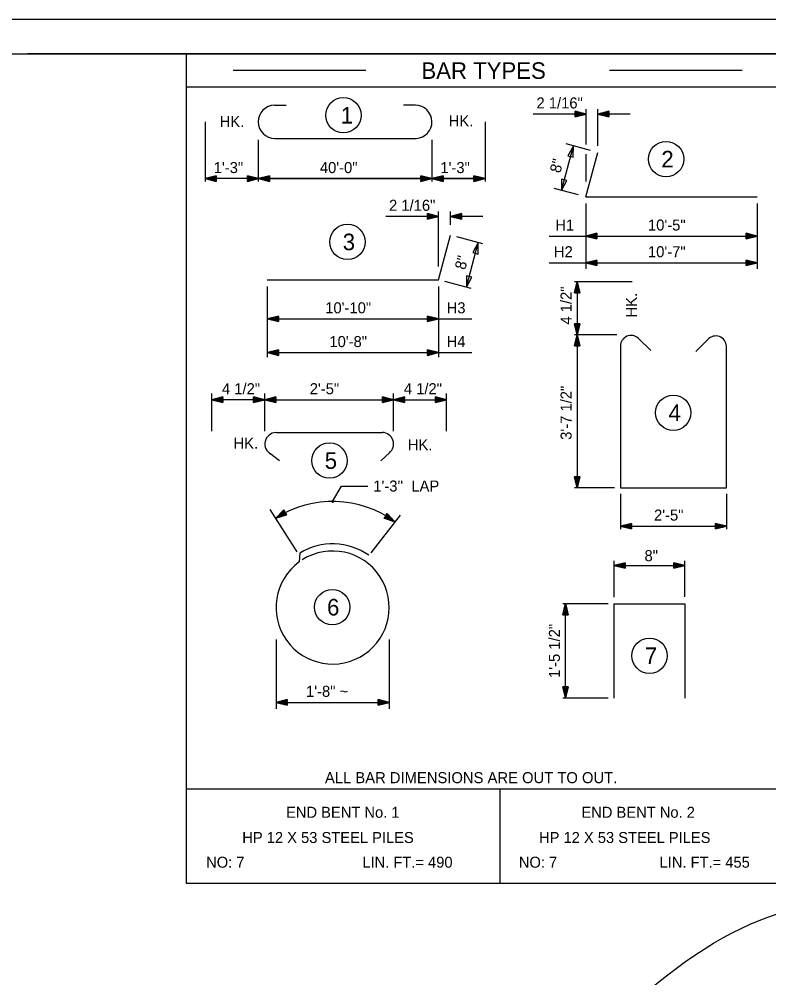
# Model space of a CAD drawing. Extents: x -41 to 191, y -168 to 6.
# Drawn here: x 45.29 to 64.69, y -142.92 to -118.09 of the extents above; entities that cross this region are included whole.
import ezdxf

# ---------------------------------------------------------------- set-up
doc = ezdxf.new("R2010")
doc.units = 0
for name, color, linetype in [('Arrowhead Terminators CELL', 7, 'Continuous'), ('Dimension Lines', 7, 'Continuous'), ('Dimension Lines CELL', 7, 'Continuous'), ('Plan Sheet CELL', 7, 'Continuous'), ('Plot Shape CELL', 7, 'Continuous'), ('Rebar Lines', 7, 'Continuous'), ('Rebar Lines CELL', 7, 'Continuous'), ('Subtitle Text', 7, 'Continuous'), ('Text', 7, 'Continuous'), ('Text CELL', 7, 'Continuous'), ('User Information Notes', 7, 'Continuous')]:
    doc.layers.add(name, color=color, linetype=linetype)

msp = doc.modelspace()

# ---------------------------------------------------------------- linework, layer by layer
at = {"layer": 'Arrowhead Terminators CELL'}
for points in [[(59.631, -121.373), (59.488, -121.631), (59.627, -121.668)], [(59.322, -122.528), (59.465, -122.27), (59.327, -122.233)], [(57.17, -123.88), (57.027, -124.138), (57.165, -124.175)], [(56.861, -125.035), (57.004, -124.777), (56.866, -124.74)]]:
    msp.add_lwpolyline(points, close=True, dxfattribs=at)
at = {"layer": 'Dimension Lines'}
for p, q in [((59.96, -120.549), (58.588, -120.549)), ((59.96, -121.342), (59.96, -120.422)), ((60.263, -121.376), (60.263, -120.422)), ((61.103, -120.549), (60.263, -120.549)), ((59.322, -122.528), (59.631, -121.373)), ((60.071, -121.491), (59.44, -121.322)), ((59.96, -122.3), (59.96, -121.589)), ((59.762, -122.645), (59.13, -122.476)), ((56.143, -124.497), (56.143, -123.071)), ((56.446, -123.423), (56.446, -123.071)), ((56.143, -123.199), (54.772, -123.199)), ((57.287, -123.199), (56.446, -123.199)), ((57.29, -123.912), (56.613, -123.731)), ((56.861, -125.035), (57.17, -123.88)), ((56.981, -125.067), (56.304, -124.886))]:
    msp.add_line(p, q, dxfattribs=at)
at = {"layer": 'Dimension Lines CELL'}
for p, q in [((50.101, -120.751), (50.101, -122.294)), ((57.343, -120.751), (57.343, -122.294)), ((51.474, -121.219), (51.474, -122.294)), ((55.97, -121.219), (55.97, -122.294)), ((51.479, -122.222), (50.101, -122.222)), ((51.479, -122.222), (55.97, -122.222)), ((57.114, -122.222), (51.479, -122.222)), ((55.97, -122.222), (57.343, -122.222)), ((59.955, -122.869), (59.955, -124.556)), ((64.385, -122.869), (64.385, -124.556)), ((59.005, -123.71), (64.385, -123.71)), ((59.005, -124.401), (64.385, -124.401)), ((51.709, -125.014), (51.709, -126.846)), ((56.139, -125.014), (56.139, -126.846)), ((61.15, -124.893), (59.656, -124.893)), ((59.727, -124.893), (59.727, -126.266)), ((51.71, -125.854), (57.002, -125.854)), ((60.751, -126.266), (59.656, -126.266)), ((59.727, -126.266), (59.727, -130.23)), ((51.71, -126.728), (57.002, -126.728)), ((50.274, -128.762), (50.274, -127.783)), ((51.646, -128.762), (51.646, -127.783)), ((54.977, -128.762), (54.977, -127.783)), ((56.35, -128.762), (56.35, -127.783)), ((51.641, -127.949), (50.274, -127.949)), ((51.641, -127.949), (54.977, -127.949)), ((54.977, -127.949), (56.35, -127.949)), ((53.399, -130.585), (53.628, -130.188)), ((53.628, -130.188), (54.314, -130.188)), ((60.693, -130.23), (59.656, -130.23)), ((60.846, -130.383), (60.846, -131.298)), ((63.592, -130.383), (63.592, -131.298)), ((52.483, -131.888), (51.786, -130.79)), ((55.151, -130.94), (54.392, -131.91)), ((60.846, -131.222), (63.592, -131.222)), ((60.686, -133.063), (60.686, -132.12)), ((60.686, -132.241), (62.516, -132.241)), ((62.516, -133.055), (62.516, -132.12)), ((60.533, -133.238), (59.354, -133.238)), ((59.425, -135.67), (59.425, -133.238)), ((51.934, -134.161), (51.934, -135.955)), ((54.863, -134.161), (54.863, -135.955)), ((51.939, -135.786), (54.868, -135.786)), ((60.533, -135.676), (59.354, -135.676))]:
    msp.add_line(p, q, dxfattribs=at)
for points in [[(59.674, -120.549), (59.674, -120.563), (59.96, -120.549), (59.674, -120.578), (59.674, -120.592), (59.96, -120.549), (59.674, -120.606), (59.674, -120.621), (59.96, -120.549), (59.674, -120.478), (59.674, -120.492), (59.96, -120.549), (59.674, -120.506), (59.674, -120.52), (59.96, -120.549), (59.674, -120.535), (59.674, -120.621), (59.674, -120.478), (59.96, -120.549), (59.674, -120.621)], [(60.549, -120.549), (60.549, -120.535), (60.263, -120.549), (60.549, -120.52), (60.549, -120.506), (60.263, -120.549), (60.549, -120.492), (60.549, -120.478), (60.263, -120.549), (60.549, -120.621), (60.549, -120.606), (60.263, -120.549), (60.549, -120.592), (60.549, -120.578), (60.263, -120.549), (60.549, -120.563), (60.549, -120.478), (60.549, -120.621), (60.263, -120.549), (60.549, -120.478)], [(50.387, -122.222), (50.387, -122.236), (50.101, -122.222), (50.387, -122.251), (50.387, -122.265), (50.101, -122.222), (50.387, -122.279), (50.387, -122.294), (50.101, -122.222), (50.387, -122.151), (50.387, -122.165), (50.101, -122.222), (50.387, -122.179), (50.387, -122.193), (50.101, -122.222), (50.387, -122.208), (50.387, -122.294), (50.387, -122.151), (50.101, -122.222), (50.387, -122.294)], [(51.193, -122.222), (51.193, -122.208), (51.479, -122.222), (51.193, -122.193), (51.193, -122.179), (51.479, -122.222), (51.193, -122.165), (51.193, -122.151), (51.479, -122.222), (51.193, -122.294), (51.193, -122.279), (51.479, -122.222), (51.193, -122.265), (51.193, -122.251), (51.479, -122.222), (51.193, -122.236), (51.193, -122.151), (51.193, -122.294), (51.479, -122.222), (51.193, -122.151)], [(51.765, -122.222), (51.765, -122.236), (51.479, -122.222), (51.765, -122.251), (51.765, -122.265), (51.479, -122.222), (51.765, -122.279), (51.765, -122.294), (51.479, -122.222), (51.765, -122.151), (51.765, -122.165), (51.479, -122.222), (51.765, -122.179), (51.765, -122.193), (51.479, -122.222), (51.765, -122.208), (51.765, -122.294), (51.765, -122.151), (51.479, -122.222), (51.765, -122.294)], [(55.684, -122.222), (55.684, -122.208), (55.97, -122.222), (55.684, -122.193), (55.684, -122.179), (55.97, -122.222), (55.684, -122.165), (55.684, -122.151), (55.97, -122.222), (55.684, -122.294), (55.684, -122.279), (55.97, -122.222), (55.684, -122.265), (55.684, -122.251), (55.97, -122.222), (55.684, -122.236), (55.684, -122.151), (55.684, -122.294), (55.97, -122.222), (55.684, -122.151)], [(56.256, -122.222), (56.256, -122.236), (55.97, -122.222), (56.256, -122.251), (56.256, -122.265), (55.97, -122.222), (56.256, -122.279), (56.256, -122.294), (55.97, -122.222), (56.256, -122.151), (56.256, -122.165), (55.97, -122.222), (56.256, -122.179), (56.256, -122.193), (55.97, -122.222), (56.256, -122.208), (56.256, -122.294), (56.256, -122.151), (55.97, -122.222), (56.256, -122.294)], [(57.057, -122.222), (57.057, -122.208), (57.343, -122.222), (57.057, -122.193), (57.057, -122.179), (57.343, -122.222), (57.057, -122.165), (57.057, -122.151), (57.343, -122.222), (57.057, -122.294), (57.057, -122.279), (57.343, -122.222), (57.057, -122.265), (57.057, -122.251), (57.343, -122.222), (57.057, -122.236), (57.057, -122.151), (57.057, -122.294), (57.343, -122.222), (57.057, -122.151)], [(55.857, -123.199), (55.857, -123.213), (56.143, -123.199), (55.857, -123.227), (55.857, -123.241), (56.143, -123.199), (55.857, -123.256), (55.857, -123.27), (56.143, -123.199), (55.857, -123.127), (55.857, -123.141), (56.143, -123.199), (55.857, -123.156), (55.857, -123.17), (56.143, -123.199), (55.857, -123.184), (55.857, -123.27), (55.857, -123.127), (56.143, -123.199), (55.857, -123.27)], [(56.732, -123.199), (56.732, -123.184), (56.446, -123.199), (56.732, -123.17), (56.732, -123.156), (56.446, -123.199), (56.732, -123.141), (56.732, -123.127), (56.446, -123.199), (56.732, -123.27), (56.732, -123.256), (56.446, -123.199), (56.732, -123.241), (56.732, -123.227), (56.446, -123.199), (56.732, -123.213), (56.732, -123.127), (56.732, -123.27), (56.446, -123.199), (56.732, -123.127)], [(60.241, -123.71), (60.241, -123.724), (59.955, -123.71), (60.241, -123.739), (60.241, -123.753), (59.955, -123.71), (60.241, -123.767), (60.241, -123.782), (59.955, -123.71), (60.241, -123.639), (60.241, -123.653), (59.955, -123.71), (60.241, -123.667), (60.241, -123.682), (59.955, -123.71), (60.241, -123.696), (60.241, -123.782), (60.241, -123.639), (59.955, -123.71), (60.241, -123.782)], [(64.099, -123.71), (64.099, -123.696), (64.385, -123.71), (64.099, -123.682), (64.099, -123.667), (64.385, -123.71), (64.099, -123.653), (64.099, -123.639), (64.385, -123.71), (64.099, -123.782), (64.099, -123.767), (64.385, -123.71), (64.099, -123.753), (64.099, -123.739), (64.385, -123.71), (64.099, -123.724), (64.099, -123.639), (64.099, -123.782), (64.385, -123.71), (64.099, -123.639)], [(60.241, -124.401), (60.241, -124.415), (59.955, -124.401), (60.241, -124.43), (60.241, -124.444), (59.955, -124.401), (60.241, -124.458), (60.241, -124.473), (59.955, -124.401), (60.241, -124.33), (60.241, -124.344), (59.955, -124.401), (60.241, -124.358), (60.241, -124.372), (59.955, -124.401), (60.241, -124.387), (60.241, -124.473), (60.241, -124.33), (59.955, -124.401), (60.241, -124.473)], [(64.099, -124.401), (64.099, -124.387), (64.385, -124.401), (64.099, -124.372), (64.099, -124.358), (64.385, -124.401), (64.099, -124.344), (64.099, -124.33), (64.385, -124.401), (64.099, -124.473), (64.099, -124.458), (64.385, -124.401), (64.099, -124.444), (64.099, -124.43), (64.385, -124.401), (64.099, -124.415), (64.099, -124.33), (64.099, -124.473), (64.385, -124.401), (64.099, -124.33)], [(59.727, -125.179), (59.713, -125.179), (59.727, -124.893), (59.699, -125.179), (59.685, -125.179), (59.727, -124.893), (59.67, -125.179), (59.656, -125.179), (59.727, -124.893), (59.799, -125.179), (59.785, -125.179), (59.727, -124.893), (59.77, -125.179), (59.756, -125.179), (59.727, -124.893), (59.742, -125.179), (59.656, -125.179), (59.799, -125.179), (59.727, -124.893), (59.656, -125.179)], [(51.996, -125.854), (51.996, -125.869), (51.71, -125.854), (51.996, -125.883), (51.996, -125.897), (51.71, -125.854), (51.996, -125.912), (51.996, -125.926), (51.71, -125.854), (51.996, -125.783), (51.996, -125.797), (51.71, -125.854), (51.996, -125.812), (51.996, -125.826), (51.71, -125.854), (51.996, -125.84), (51.996, -125.926), (51.996, -125.783), (51.71, -125.854), (51.996, -125.926)], [(55.853, -125.854), (55.853, -125.84), (56.139, -125.854), (55.853, -125.826), (55.853, -125.812), (56.139, -125.854), (55.853, -125.797), (55.853, -125.783), (56.139, -125.854), (55.853, -125.926), (55.853, -125.912), (56.139, -125.854), (55.853, -125.897), (55.853, -125.883), (56.139, -125.854), (55.853, -125.869), (55.853, -125.783), (55.853, -125.926), (56.139, -125.854), (55.853, -125.783)], [(59.727, -125.98), (59.742, -125.98), (59.727, -126.266), (59.756, -125.98), (59.77, -125.98), (59.727, -126.266), (59.785, -125.98), (59.799, -125.98), (59.727, -126.266), (59.656, -125.98), (59.67, -125.98), (59.727, -126.266), (59.685, -125.98), (59.699, -125.98), (59.727, -126.266), (59.713, -125.98), (59.799, -125.98), (59.656, -125.98), (59.727, -126.266), (59.799, -125.98)], [(59.727, -126.552), (59.713, -126.552), (59.727, -126.266), (59.699, -126.552), (59.685, -126.552), (59.727, -126.266), (59.67, -126.552), (59.656, -126.552), (59.727, -126.266), (59.799, -126.552), (59.785, -126.552), (59.727, -126.266), (59.77, -126.552), (59.756, -126.552), (59.727, -126.266), (59.742, -126.552), (59.656, -126.552), (59.799, -126.552), (59.727, -126.266), (59.656, -126.552)], [(51.996, -126.728), (51.996, -126.743), (51.71, -126.728), (51.996, -126.757), (51.996, -126.771), (51.71, -126.728), (51.996, -126.786), (51.996, -126.8), (51.71, -126.728), (51.996, -126.657), (51.996, -126.671), (51.71, -126.728), (51.996, -126.686), (51.996, -126.7), (51.71, -126.728), (51.996, -126.714), (51.996, -126.8), (51.996, -126.657), (51.71, -126.728), (51.996, -126.8)], [(55.853, -126.728), (55.853, -126.714), (56.139, -126.728), (55.853, -126.7), (55.853, -126.686), (56.139, -126.728), (55.853, -126.671), (55.853, -126.657), (56.139, -126.728), (55.853, -126.8), (55.853, -126.786), (56.139, -126.728), (55.853, -126.771), (55.853, -126.757), (56.139, -126.728), (55.853, -126.743), (55.853, -126.657), (55.853, -126.8), (56.139, -126.728), (55.853, -126.657)], [(50.56, -127.949), (50.56, -127.963), (50.274, -127.949), (50.56, -127.977), (50.56, -127.991), (50.274, -127.949), (50.56, -128.006), (50.56, -128.02), (50.274, -127.949), (50.56, -127.877), (50.56, -127.891), (50.274, -127.949), (50.56, -127.906), (50.56, -127.92), (50.274, -127.949), (50.56, -127.934), (50.56, -128.02), (50.56, -127.877), (50.274, -127.949), (50.56, -128.02)], [(51.355, -127.949), (51.355, -127.934), (51.641, -127.949), (51.355, -127.92), (51.355, -127.906), (51.641, -127.949), (51.355, -127.891), (51.355, -127.877), (51.641, -127.949), (51.355, -128.02), (51.355, -128.006), (51.641, -127.949), (51.355, -127.991), (51.355, -127.977), (51.641, -127.949), (51.355, -127.963), (51.355, -127.877), (51.355, -128.02), (51.641, -127.949), (51.355, -127.877)], [(51.927, -127.949), (51.927, -127.963), (51.641, -127.949), (51.927, -127.977), (51.927, -127.991), (51.641, -127.949), (51.927, -128.006), (51.927, -128.02), (51.641, -127.949), (51.927, -127.877), (51.927, -127.891), (51.641, -127.949), (51.927, -127.906), (51.927, -127.92), (51.641, -127.949), (51.927, -127.934), (51.927, -128.02), (51.927, -127.877), (51.641, -127.949), (51.927, -128.02)], [(54.691, -127.949), (54.691, -127.934), (54.977, -127.949), (54.691, -127.92), (54.691, -127.906), (54.977, -127.949), (54.691, -127.891), (54.691, -127.877), (54.977, -127.949), (54.691, -128.02), (54.691, -128.006), (54.977, -127.949), (54.691, -127.991), (54.691, -127.977), (54.977, -127.949), (54.691, -127.963), (54.691, -127.877), (54.691, -128.02), (54.977, -127.949), (54.691, -127.877)], [(55.263, -127.949), (55.263, -127.963), (54.977, -127.949), (55.263, -127.977), (55.263, -127.991), (54.977, -127.949), (55.263, -128.006), (55.263, -128.02), (54.977, -127.949), (55.263, -127.877), (55.263, -127.891), (54.977, -127.949), (55.263, -127.906), (55.263, -127.92), (54.977, -127.949), (55.263, -127.934), (55.263, -128.02), (55.263, -127.877), (54.977, -127.949), (55.263, -128.02)], [(56.064, -127.949), (56.064, -127.934), (56.35, -127.949), (56.064, -127.92), (56.064, -127.906), (56.35, -127.949), (56.064, -127.891), (56.064, -127.877), (56.35, -127.949), (56.064, -128.02), (56.064, -128.006), (56.35, -127.949), (56.064, -127.991), (56.064, -127.977), (56.35, -127.949), (56.064, -127.963), (56.064, -127.877), (56.064, -128.02), (56.35, -127.949), (56.064, -127.877)], [(59.727, -129.944), (59.742, -129.944), (59.727, -130.23), (59.756, -129.944), (59.77, -129.944), (59.727, -130.23), (59.785, -129.944), (59.799, -129.944), (59.727, -130.23), (59.656, -129.944), (59.67, -129.944), (59.727, -130.23), (59.685, -129.944), (59.699, -129.944), (59.727, -130.23), (59.713, -129.944), (59.799, -129.944), (59.656, -129.944), (59.727, -130.23), (59.799, -129.944)], [(52.17, -130.865), (52.178, -130.877), (51.926, -131.013), (52.185, -130.889), (52.193, -130.902), (51.926, -131.013), (52.2, -130.914), (52.207, -130.926), (51.926, -131.013), (52.133, -130.804), (52.141, -130.816), (51.926, -131.013), (52.148, -130.828), (52.156, -130.841), (51.926, -131.013), (52.163, -130.853), (52.207, -130.926), (52.133, -130.804), (51.926, -131.013), (52.207, -130.926)], [(54.773, -130.953), (54.78, -130.941), (55.013, -131.109), (54.788, -130.929), (54.796, -130.917), (55.013, -131.109), (54.804, -130.905), (54.812, -130.893), (55.013, -131.109), (54.734, -131.013), (54.742, -131.001), (55.013, -131.109), (54.749, -130.989), (54.757, -130.977), (55.013, -131.109), (54.765, -130.965), (54.812, -130.893), (54.734, -131.013), (55.013, -131.109), (54.812, -130.893)], [(61.132, -131.222), (61.132, -131.236), (60.846, -131.222), (61.132, -131.251), (61.132, -131.265), (60.846, -131.222), (61.132, -131.279), (61.132, -131.293), (60.846, -131.222), (61.132, -131.15), (61.132, -131.165), (60.846, -131.222), (61.132, -131.179), (61.132, -131.193), (60.846, -131.222), (61.132, -131.208), (61.132, -131.293), (61.132, -131.15), (60.846, -131.222), (61.132, -131.293)], [(63.306, -131.222), (63.306, -131.208), (63.592, -131.222), (63.306, -131.193), (63.306, -131.179), (63.592, -131.222), (63.306, -131.165), (63.306, -131.15), (63.592, -131.222), (63.306, -131.293), (63.306, -131.279), (63.592, -131.222), (63.306, -131.265), (63.306, -131.251), (63.592, -131.222), (63.306, -131.236), (63.306, -131.15), (63.306, -131.293), (63.592, -131.222), (63.306, -131.15)], [(60.972, -132.241), (60.972, -132.255), (60.686, -132.241), (60.972, -132.269), (60.972, -132.284), (60.686, -132.241), (60.972, -132.298), (60.972, -132.312), (60.686, -132.241), (60.972, -132.169), (60.972, -132.184), (60.686, -132.241), (60.972, -132.198), (60.972, -132.212), (60.686, -132.241), (60.972, -132.226), (60.972, -132.312), (60.972, -132.169), (60.686, -132.241), (60.972, -132.312)], [(62.23, -132.241), (62.23, -132.226), (62.516, -132.241), (62.23, -132.212), (62.23, -132.198), (62.516, -132.241), (62.23, -132.184), (62.23, -132.169), (62.516, -132.241), (62.23, -132.312), (62.23, -132.298), (62.516, -132.241), (62.23, -132.284), (62.23, -132.269), (62.516, -132.241), (62.23, -132.255), (62.23, -132.169), (62.23, -132.312), (62.516, -132.241), (62.23, -132.169)], [(59.425, -133.516), (59.411, -133.516), (59.425, -133.23), (59.397, -133.516), (59.382, -133.516), (59.425, -133.23), (59.368, -133.516), (59.354, -133.516), (59.425, -133.23), (59.497, -133.516), (59.483, -133.516), (59.425, -133.23), (59.468, -133.516), (59.454, -133.516), (59.425, -133.23), (59.44, -133.516), (59.354, -133.516), (59.497, -133.516), (59.425, -133.23), (59.354, -133.516)], [(59.425, -135.384), (59.44, -135.384), (59.425, -135.67), (59.454, -135.384), (59.468, -135.384), (59.425, -135.67), (59.483, -135.384), (59.497, -135.384), (59.425, -135.67), (59.354, -135.384), (59.368, -135.384), (59.425, -135.67), (59.382, -135.384), (59.397, -135.384), (59.425, -135.67), (59.411, -135.384), (59.497, -135.384), (59.354, -135.384), (59.425, -135.67), (59.497, -135.384)], [(52.225, -135.786), (52.225, -135.801), (51.939, -135.786), (52.225, -135.815), (52.225, -135.829), (51.939, -135.786), (52.225, -135.843), (52.225, -135.858), (51.939, -135.786), (52.225, -135.715), (52.225, -135.729), (51.939, -135.786), (52.225, -135.743), (52.225, -135.758), (51.939, -135.786), (52.225, -135.772), (52.225, -135.858), (52.225, -135.715), (51.939, -135.786), (52.225, -135.858)], [(54.582, -135.786), (54.582, -135.772), (54.868, -135.786), (54.582, -135.758), (54.582, -135.743), (54.868, -135.786), (54.582, -135.729), (54.582, -135.715), (54.868, -135.786), (54.582, -135.858), (54.582, -135.843), (54.868, -135.786), (54.582, -135.829), (54.582, -135.815), (54.868, -135.786), (54.582, -135.801), (54.582, -135.715), (54.582, -135.858), (54.868, -135.786), (54.582, -135.715)]]:
    msp.add_lwpolyline(points, dxfattribs=at)
for centre, radius in [((53.678, -120.582), 0.458), ((62.029, -121.717), 0.458), ((53.783, -123.862), 0.458), ((62.215, -128.286), 0.458), ((53.317, -129.525), 0.458), ((53.4, -130.585), 0.0229), ((53.389, -133.321), 0.458), ((61.601, -134.579), 0.458)]:
    msp.add_circle(centre, radius, dxfattribs=at)
msp.add_arc((53.399, -133.33), 2.746, 54.0023, 122.4453, dxfattribs=at)
at = {"layer": 'Plan Sheet CELL'}
for p, q in [((2.412, -118.994), (75.628, -118.994)), ((75.628, -118.994), (45.504, -118.994)), ((49.605, -118.994), (49.605, -140.465)), ((54.256, -119.424), (50.824, -119.424)), ((63.997, -119.424), (60.565, -119.424)), ((65.332, -119.853), (49.605, -119.853)), ((49.605, -138.022), (65.332, -138.022)), ((57.731, -138.022), (57.731, -140.465)), ((49.605, -140.465), (75.628, -140.465))]:
    msp.add_line(p, q, dxfattribs=at)
at = {"layer": 'Plot Shape CELL'}
msp.add_lwpolyline([(0, -118.093), (75.648, -118.093), (75.648, -168.429), (0, -168.429)], close=True, dxfattribs=at)
at = {"layer": 'Rebar Lines'}
for p, q in [((59.953, -122.697), (60.263, -121.542)), ((56.137, -124.841), (56.446, -123.686))]:
    msp.add_line(p, q, dxfattribs=at)
at = {"layer": 'Rebar Lines CELL'}
for p, q in [((51.896, -120.322), (52.201, -120.322)), ((55.541, -120.322), (55.236, -120.322)), ((51.903, -121.18), (55.564, -121.18)), ((59.953, -122.697), (64.383, -122.697)), ((51.707, -124.841), (56.137, -124.841)), ((61.633, -126.677), (61.308, -126.352)), ((63.11, -126.388), (62.798, -126.7)), ((51.943, -128.796), (54.689, -128.796)), ((52.026, -129.528), (51.764, -129.33)), ((54.644, -129.528), (54.881, -129.312)), ((52.547, -131.92), (52.532, -132.15))]:
    msp.add_line(p, q, dxfattribs=at)
for points in [[(60.846, -126.56), (60.846, -130.23), (63.592, -130.23), (63.592, -126.565)], [(60.686, -135.676), (60.686, -133.236), (62.516, -133.236), (62.516, -135.676)]]:
    msp.add_lwpolyline(points, dxfattribs=at)
for centre, radius, start, end in [((51.903, -120.751), 0.429, 90.9575, 270), ((55.541, -120.751), 0.429, 272.972, 90), ((61.123, -126.56), 0.277, 48.347, 179.1529), ((63.315, -126.574), 0.277, 1.7953, 137.8717), ((51.943, -129.093), 0.297, 91.6756, 242.6185), ((54.68, -129.093), 0.297, 309.3145, 88.3244), ((53.399, -133.33), 1.647, 55.2112, 121.1302), ((53.399, -133.33), 1.464, 126.3141, 122.4154)]:
    msp.add_arc(centre, radius, start, end, dxfattribs=at)
at = {"layer": 'User Information Notes'}
msp.add_ellipse((62.956, -146.039), major_axis=(4.526, 4.526), ratio=0.46622, dxfattribs=at)

# ---------------------------------------------------------------- texts
at = {"layer": 'Plan Sheet CELL'}
msp.add_text('BAR TYPES', height=0.429, dxfattribs=at).set_placement((55.697, -119.639))
at = {"layer": 'Subtitle Text'}
for s, p in [('1', (53.611, -120.797)), ('2', (61.907, -121.932)), ('3', (53.661, -124.076)), ('4', (62.093, -128.5)), ('5', (53.195, -129.739)), ('6', (53.255, -133.536)), ('7', (61.479, -134.794))]:
    msp.add_text(s, height=0.429, dxfattribs=at).set_placement(p)
at = {"layer": 'Text'}
for s, height, p in [('2 1/16"', 0.286, (58.675, -120.406)), ('1\'-3"', 0.286, (50.322, -122.079)), ('40\'-0"', 0.286, (53.069, -122.079)), ('1\'-3"', 0.286, (56.188, -122.079)), ('2 1/16"', 0.286, (54.859, -123.056)), ('H1', 0.286, (59.162, -123.567)), ('10\'-5"', 0.286, (61.561, -123.567)), ('H2', 0.286, (59.126, -124.258)), ('10\'-7"', 0.286, (61.561, -124.258)), ('10\'-10"', 0.286, (53.208, -125.711)), ('H3', 0.286, (56.35, -125.711)), ('10\'-8"', 0.286, (53.315, -126.585)), ('H4', 0.286, (56.35, -126.585)), ('4 1/2"', 0.286, (50.535, -127.806)), ('2\'-5"', 0.286, (52.807, -127.806)), ('4 1/2"', 0.286, (55.242, -127.806)), ('2\'-5"', 0.286, (61.717, -131.079)), ('8"', 0.286, (61.471, -132.13)), ('1\'-8" ~', 0.286, (52.711, -135.643)), ('ALL BAR DIMENSIONS ARE OUT TO OUT.', 0.286, (53.201, -137.879)), ('END BENT No. 1', 0.28433, (52.194, -138.775)), ('END BENT No. 2', 0.28433, (59.838, -138.775)), ('HP 12 X 53 STEEL PILES', 0.28433, (51.061, -139.428)), ('HP 12 X 53 STEEL PILES', 0.28433, (58.741, -139.428)), ('NO: 7', 0.2843, (50.125, -140.068)), ('LIN. FT.= 490', 0.28433, (54.168, -140.068)), ('NO: 7', 0.2843, (58.218, -140.068)), ('LIN. FT.= 455', 0.28433, (61.861, -140.068))]:
    msp.add_text(s, height=height, dxfattribs=at).set_placement(p)
for s, rotation, p in [('8"', 75, (59.29, -122.094)), ('8"', 75, (56.829, -124.601)), ('4 1/2"', 90, (59.584, -126.002)), ('3\'-7 1/2"', 90, (59.584, -128.986)), ('1\'-5 1/2"', 90, (59.282, -135.154))]:
    msp.add_text(s, height=0.286, rotation=rotation, dxfattribs=at).set_placement(p)
at = {"layer": 'Text CELL'}
for s, p in [('HK.', (50.475, -120.888)), ('HK.', (56.403, -120.87)), ('HK.', (50.835, -129.219)), ('HK.', (55.345, -129.257)), ("1'-3''  LAP", (54.452, -130.327))]:
    msp.add_text(s, height=0.286, dxfattribs=at).set_placement(p)
msp.add_text('HK.', height=0.286, rotation=90, dxfattribs=at).set_placement((61.274, -125.817))

doc.saveas('drawing.dxf')
